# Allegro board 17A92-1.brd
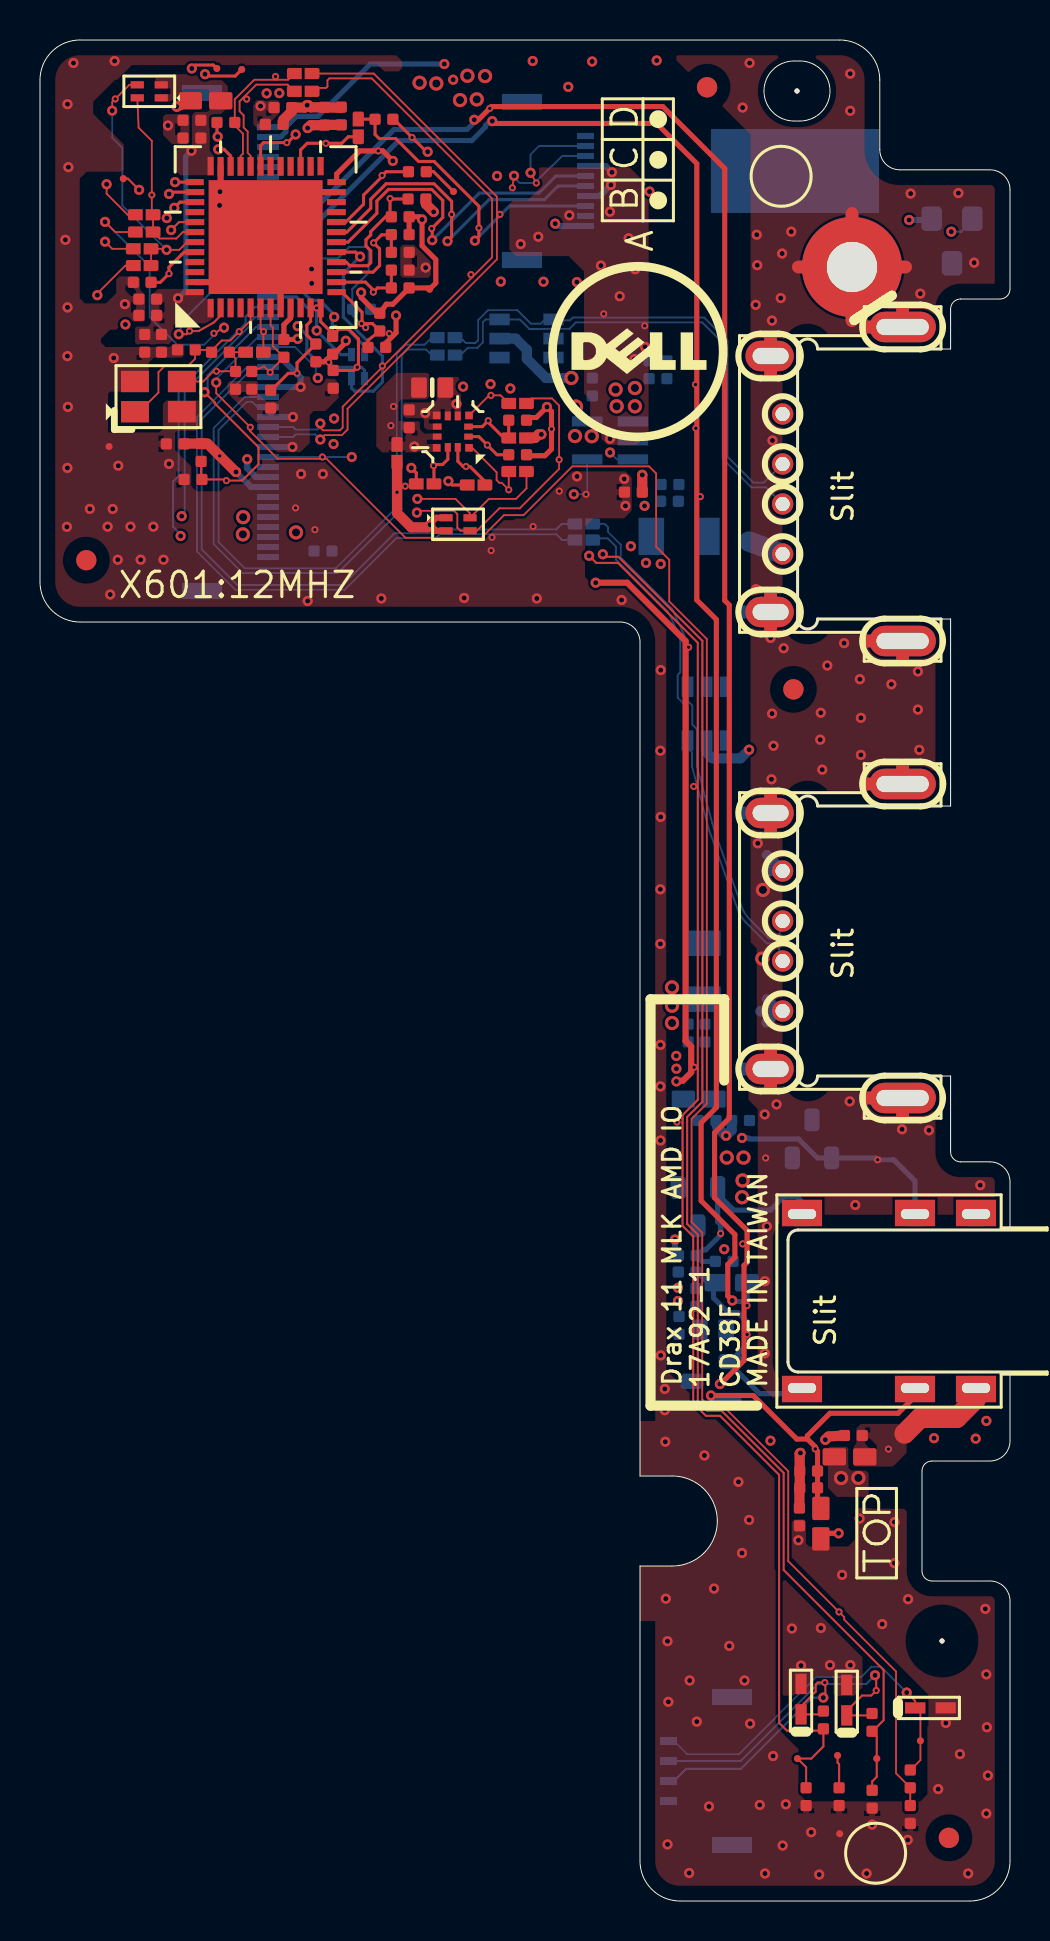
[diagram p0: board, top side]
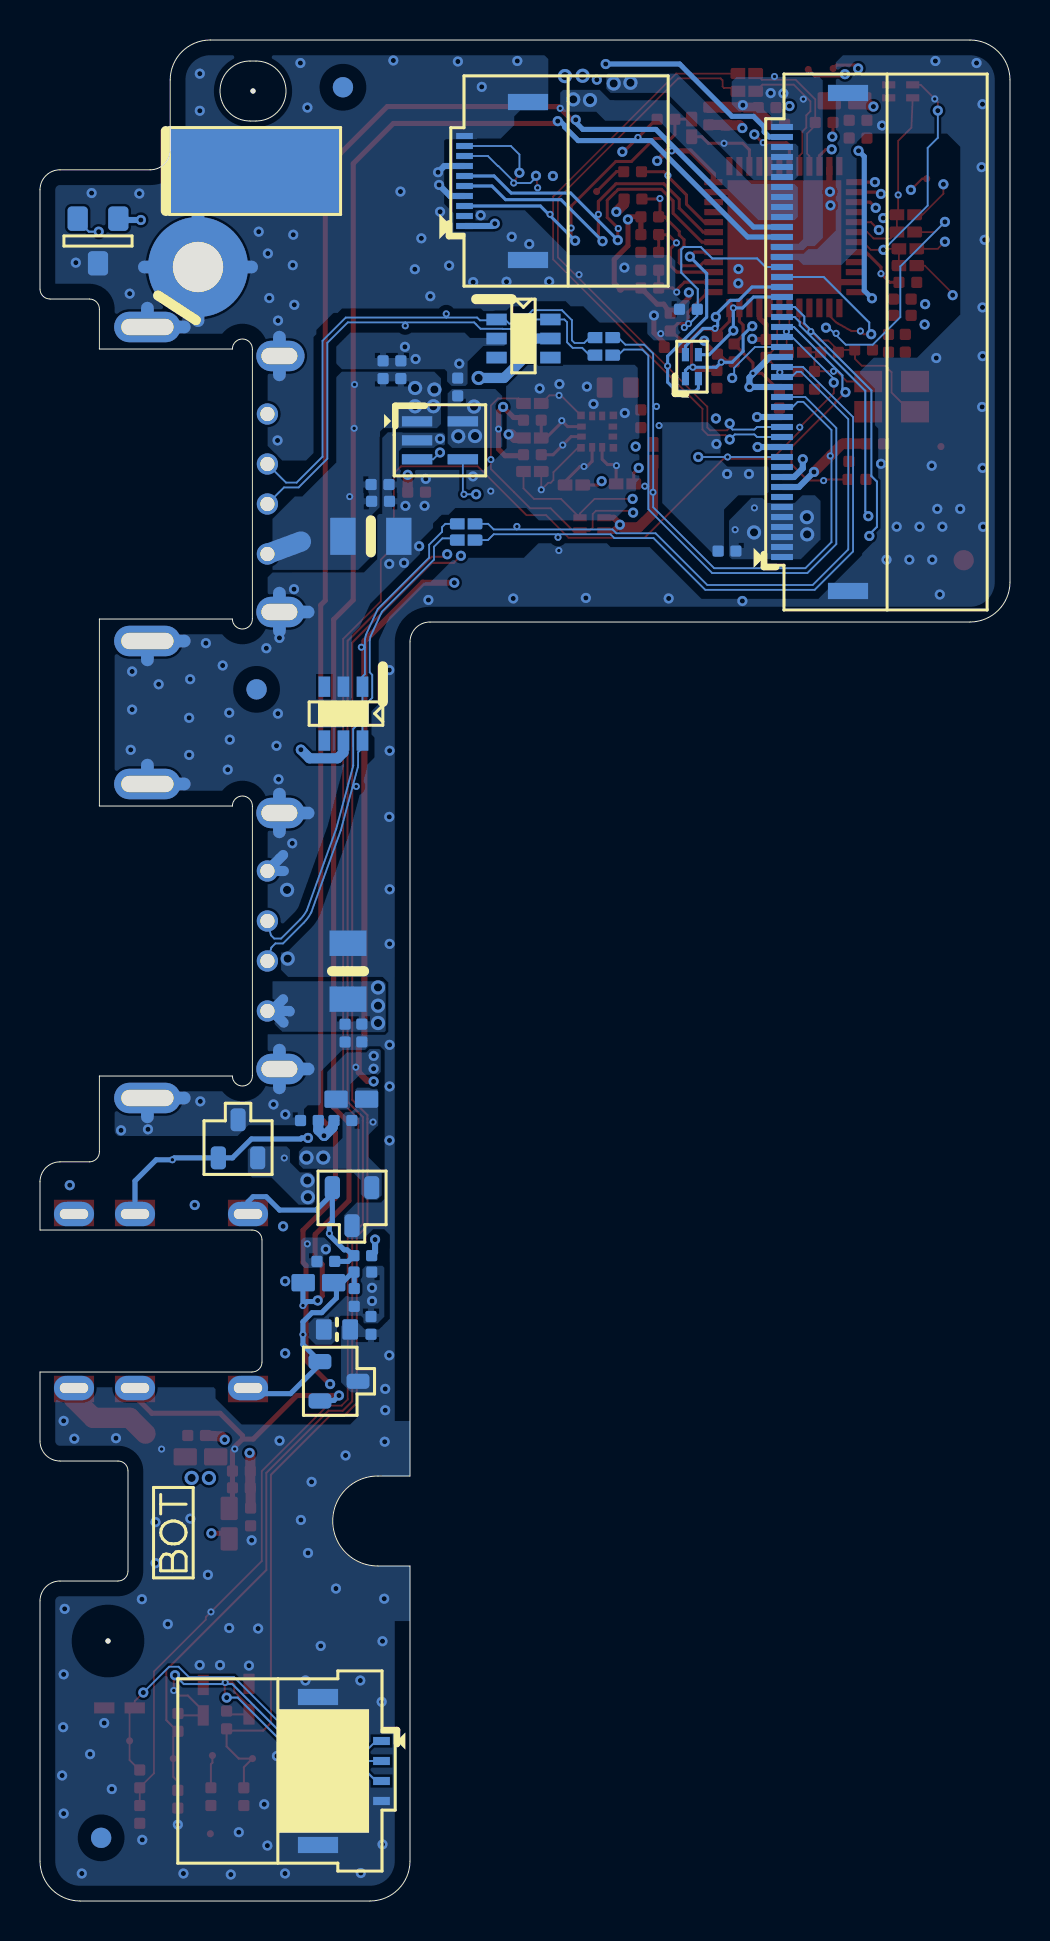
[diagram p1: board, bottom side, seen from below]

Outline 48.5 x 93.05 mm; copper layers: TOP, L2GND, L3, L4, L5VCC, BOTTOM. Coordinates in mm from the lower left corner of the outline.
Outline path: 0,91.05 0,65.95 arc(0.59,64.54) 2,63.95 29,63.95 arc(29.71,63.66) 30,62.95 30,21.25 31.6,21.25 arc(33.85,19) 31.6,16.75 30,16.75 30,2 arc(30.59,0.59) 32,0 46.5,0 arc(47.91,0.59) 48.5,2 48.5,15 arc(48.21,15.71) 47.5,16 44.6,16 arc(44.25,16.15) 44.1,16.5 44.1,21.5 arc(44.25,21.85) 44.6,22 47.5,22 arc(48.21,22.29) 48.5,23 48.5,26.45 37.9,26.45 arc(37.55,26.6) 37.4,26.95 37.4,33.05 arc(37.55,33.4) 37.9,33.55 48.5,33.55 48.5,35.96 arc(48.21,36.66) 47.5,36.96 46.03,36.96 arc(45.68,37.1) 45.53,37.46 45.53,41.25 38.88,41.25 arc(38.38,40.75) 37.88,41.25 37.88,54.75 arc(38.38,55.25) 38.88,54.75 45.53,54.75 45.53,64.1 38.88,64.1 arc(38.38,63.6) 37.88,64.1 37.88,77.6 arc(38.38,78.1) 38.88,77.6 45.53,77.6 45.53,79.6 arc(45.68,79.95) 46.03,80.1 48,80.1 arc(48.35,80.25) 48.5,80.6 48.5,85.56 arc(48.21,86.27) 47.5,86.56 42.99,86.56 arc(42.28,86.85) 41.99,87.56 41.99,91.05 arc(41.4,92.46) 39.99,93.05 2,93.05 arc(0.59,92.46) 0,91.05 ; 37.7,92 38,92 arc(39.5,90.5) 38,89 37.7,89 arc(36.2,90.5) 37.7,92

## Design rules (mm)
constraint set DEFAULT: min track width 0.127, pair gap 0.102
net group HUB_USB20_CON_N7: nets HUB_USB20_CON_N7 USB_2-
net group HUB_USB20_CON_P7: nets HUB_USB20_CON_P7 USB_2+
net group POWER_20M: nets 3D3V_S0 3D3V_S5
net group AUDIO_BEEP: nets AUD_PORTA_L_HPMIC1 AUD_PORTA_L_R_B AUD_PORTA_R_HPMIC1 AUD_PORTA_R_R_B JACK_PLUG JACK_PLUG_DET
net group OTHER: nets KBC_PWRBTN# KBC_PWRBTN#_C USB_OC#0 USB_PWR_EN#
net group OTHER_4: nets HALL_KB_DIS# HALL_KB_DIS#_C KB_RESERVE MODEL_ID SENSOR_KB_DIS VOL_DOWN# VOL_DOWN#_R VOL_UP# VOL_UP#_R
net group SENSOR: nets GSEN2_INT1 GSEN2_INT1_C GSEN2_INT1_R GSEN2_INT2 GSEN2_INT2_C GSEN2_INT2_R GSEN_INT1_BD GSEN_INT2_BD GSEN_INT2_HUB_U GSENSOR_CS GSENSOR_SDO GYRO_DRDY_BD GYRO_DRDY_BD_L GYRO_INT_BD GYRO_INT_BD_L HUB_PA1 HUB_PA2 HUB_PA3 HUB_PA4 HUB_PA5 HUB_PA6 MCU_BOOT0 SWCLK SWDIO USBDISABLE
net group SMBUS_CLK-MW: nets SENSOR_I2C_SCL SENSOR_I2C_SCL_2G SENSOR_I2C_SCL_R ST_SENSOR_I2C_SCL
net group SMBUS_DAT-MW: nets SENSOR_I2C_SDA SENSOR_I2C_SDA_2G SENSOR_I2C_SDA_R ST_SENSOR_I2C_SDA
net group USB_HUB-MWS: nets MCU_RST#
net group XTAL: nets MCU_OSCI MCU_OSCO MCU_OSCO_X601

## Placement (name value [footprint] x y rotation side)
AFTP701  AFTE14P-GP  [AFTE14P-75]  39.98 3.36 0 top
AFTP702  AFTE14P-GP  [AFTE14P-75]  44.02 8.01 0 top
AFTP703  AFTE14P-GP  [AFTE14P-75]  41.84 7.12 0 top
AFTP704  AFTE14P-GP  [AFTE14P-75]  37.87 7.12 0 top
AFTP706  AFTE14P-GP  [AFTE14P-75]  39.88 7.27 0 top
C402  SCD1U16V2KX-3GP  [C402H22]  30.46 76.56 0 bottom
C403  SC1U10V2KX-1GP  [C402H22]  27.61 75.7 0 bottom
C404  SC1U10V2KX-1GP  [C402H22]  31.35 76.56 0 bottom
C405  SC100U6D3V6MX-GP  [C1206H71]  33.1 46.49 0 bottom
C406  SC100U6D3V6MX-GP  [C1206H71]  31.96 68.23 90 bottom
C407  SCD1U16V2KX-3GP  [C402H22]  32.41 43.4 180 bottom
C501  SC10U6D3V3MX-GP  [C603H38]  19.61 75.67 90 top
C502  SCD1U16V2KX-3GP  [C402H22]  18.46 74.11 180 top
C601  SC15P50V2JN-2-GP  [C402H22]  9.78 76.03 0 top
C602  SCD01U50V2KX-1GP  [C402H22]  5.39 80.1 270 top
C603  SC15P50V2JN-2-GP  [C402H22]  7.32 77.56 270 top
C604  SCD1U16V2KX-3GP  [C402H22]  5.39 79.28 270 top
C605  SC1U10V2KX-1GP  [C402H22]  7.6 89.04 270 top
C606  SCD1U16V2KX-3GP  [C402H22]  7.6 88.15 270 top
C607  SCD1U16V2KX-3GP  [C402H22]  6.07 77.89 0 top
C608  SCD1U16V2KX-3GP  [C402H22]  10.59 76.03 0 top
C609  SCD1U16V2KX-3GP  [C402H22]  5.24 77.89 0 top
C610  SCD1U16V2KX-3GP  [C402H22]  6.76 72.86 270 top
C611  SCD047U16V2KX-1-GP  [C402H22]  7.65 71.08 270 top
C702  SC1KP50V2KX-1GP  [C402H22]  38.31 5.22 180 top
C703  SC1KP50V2KX-1GP  [C402H22]  41.61 5.09 180 top
C704  SCD1U25V2KX-GP  [C402H22]  43.51 4.33 0 top
C801  SCD1U10V2KX-L1-GP  [C402H22]  14.15 67.5 270 bottom
EC301  SC680P50V2KX-2DLGP  [C402H22]  33.35 39.02 270 bottom
EC302  SC680P50V2KX-2DLGP  [C402H22]  32.79 30.18 180 bottom
EC303  SC680P50V2KX-2DLGP  [C402H22]  40.67 23.28 270 top
EC304  SC680P50V2KX-2DLGP  [C402H22]  38.43 21.5 270 top
EC401  SCD1U16V2KX-3GP  [C402H22]  31.5 70.82 90 bottom
EC402  SCD1U16V2KX-3GP  [C402H22]  31.47 69.99 90 bottom
EC705  SCD1U16V2KX-3GP  [C402H22]  39.95 5.22 0 top
EC801  SCD1U25V2KX-1-DL-GP  [C402H22]  14.23 89.24 0 top
EC802  SCD1U25V2KX-1-DL-GP  [C402H22]  35.03 39.02 270 bottom
EC803  SCD1U25V2KX-1-DL-GP  [C402H22]  11.71 88.83 270 top
EC804  SCD1U25V2KX-1-DL-GP  [C402H22]  31.95 28.78 180 bottom
EC805  SCD1U25V2KX-1-DL-GP  [C402H22]  15.06 89.25 0 top
EC806  SCD1U25V2KX-1-DL-GP  [C402H22]  12.14 89.67 270 top
EC807  SCD1U25V2KX-1-DL-GP  [C402H22]  37.97 19.2 0 top
EC808  SCD1U25V2KX-1-DL-GP  [C402H22]  29.67 70.44 270 top
ED301  AZ5125-02S-R7G-GP  [SOT23-2D4-312H46]  33.55 25.99 270 bottom
ED302  AZ5125-02S-R7G-GP  [SOT23-2D4-312H46]  38.6 38.11 180 bottom
ED303  AZ5125-02S-R7G-GP  [SOT23-2D4-312H46]  32.9 34.72 0 bottom
ED402  AZC099-04S-2-GP  [SOT-6H58]  24.33 78.12 270 bottom
ED403  AZC099-04S-2-GP  [SOT-6H58]  33.33 59.37 0 bottom
ED701  PESD5V0S1BB-GP-U  [SOD-523-2H26]  44.52 9.65 90 top
ED702  PESD5V0S1BB-GP-U  [SOD-523-2H26]  40.34 10.04 180 top
ED703  PESD5V0S1BB-GP-U  [SOD-523-2H26]  38.05 10.09 180 top
H7  HOLE197R99-GP  [HOLE197R99]  40.6 81.7 0 top
HPMIC1  AUDIO-JK489-GP  [AJ3F7C-YX50-412]  46.8 30 90 top
IOBD2  ACES-CON44-2-GP  [132F44-000000-A2-R]  8.1 77.95 90 bottom
LIDSW2  S-5712ACDL1-M3T1U-GP  [SOT23-2D8-123H52]  45.6 83 0 bottom
NOREF  -  []  29.39 87.82 90 top
NOREF#2  -  []  41.78 2.39 0 top
NOREF#3  *  [unnamed#2]  45.44 3.16 0 top
NOREF#4  -  [unnamed#2]  37.85 90.5 0 top
NOREF#5  -  []  29.89 77.47 0 top
NOREF#6  *  [unnamed#2]  33.35 90.69 0 top
NOREF#7  -  []  -91.9 111 0 top
NOREF#8  -  [unnamed#2]  45.1 13 0 top
NOREF#9  *  [unnamed#2]  2.32 67.04 0 top
NOREF#10  -  []  -91.9 111 0 top
NOREF#11  -  []  41.83 18.39 90 top
NOREF#12  -  []  519.62 509.67 0 top
NOREF#13  *  [unnamed#2]  37.67 60.58 0 top
NOREF#14  -  []  37.06 86.24 0 top
NOREF#15  *  [unnamed#2]  33.35 90.69 180 bottom
NOREF#16  -  []  41.83 18.42 90 bottom
NOREF#17  *  [unnamed#2]  37.67 60.58 180 bottom
NOREF#18  *  [unnamed#2]  45.44 3.16 180 bottom
PWBD1  ACES-CON4-83-GP  [51678-00401-W01]  34.6 6.5 270 bottom
R301  -  [0R0603-PAD]  32.84 40.09 90 bottom
R302  -  [0R0603-PAD]  34.49 30.91 90 bottom
R303  -  [0R0603-PAD]  39.04 18.96 180 top
R304  10KR2J-3-GP  [R402H16]  32.36 31.45 90 bottom
R305  10KR2J-3-GP  [R402H16]  38.43 20.66 270 top
R306  -  [0R0603-PAD]  40.57 22.21 90 top
R307  0R2J-L-GP  [R402H15]  34.21 31.98 270 bottom
R308  0R2J-L-GP  [R402H15]  32.36 32.27 270 bottom
R406  100KR2J-1-GP  [R402H16]  33.25 43.39 180 bottom
R407  -  [0R0402-PAD]  20.31 77.29 270 bottom
R408  -  [0R0402-PAD]  20.31 78.17 270 bottom
R409  -  [0R0402-PAD]  27.19 68.05 270 bottom
R410  -  [0R0402-PAD]  27.19 68.86 270 bottom
R501  -  [0R0402-PAD]  17.85 72.38 180 top
R502  10KR2J-3-GP  [R402H16]  23.88 74.04 270 top
R503  -  [0R0402-PAD]  23.88 73.15 270 top
R504  10KR2J-3-GP  [R402H16]  23.88 72.31 270 top
R505  -  [0R0402-PAD]  21.8 70.8 270 top
R506  -  [0R0402-PAD]  19.25 70.86 270 top
R507  -  [0R0402-PAD]  23.88 71.47 270 top
R508  -  [0R0402-PAD]  23.88 74.88 270 top
R601  -  [0R0402-PAD]  13.16 90.48 270 top
R602  20MR2J-1-GP  [R402H16]  9.02 77.44 270 top
R603  1K5R2F-2-GP  [R402H16]  9.29 88.93 270 top
R604  10KR2J-3-GP  [R402H16]  14.63 77.78 0 top
R605  10KR2J-3-GP  [R402H16]  11.53 75.09 180 top
R606  10KR2J-3-GP  [R402H16]  13.79 77.4 0 top
R607  10KR2J-3-GP  [R402H16]  18.85 85.1 270 top
R608  10KR2J-3-GP  [R402H16]  18.01 82.43 270 top
R609  10KR2J-3-GP  [R402H16]  18.01 84.21 90 top
R610  10KR2J-3-GP  [R402H16]  18.01 81.54 270 top
R611  10KR2J-3-GP  [R402H16]  18.01 83.32 90 top
R612  10KR2J-3-GP  [R402H16]  18.01 80.65 90 top
R613  10KR2J-3-GP  [R402H16]  16.84 77.68 270 top
R614  10KR2J-3-GP  [R402H16]  16.99 78.95 180 top
R615  100KR2J-1-GP  [R402H16]  12.19 77.63 180 top
R616  10KR2J-3-GP  [R402H16]  14.66 76.08 180 top
R617  -  [0R0402-PAD]  13.16 91.37 270 top
R618  20KR2J-L2-GP  [R402H16]  5.11 80.93 270 top
R619  -  [0R0603-PAD]  8.36 90.01 90 top
R620  100KR2J-1-GP  [R402H16]  8.05 72.42 180 top
R621  -  [0R0402-PAD]  5.21 84.31 90 top
R622  -  [0R0402-PAD]  5.21 83.45 90 top
R623  -  [0R0402-PAD]  5.11 82.61 90 top
R624  -  [0R0402-PAD]  5.11 81.77 90 top
R625  -  [0R0402-PAD]  10.72 77.44 270 top
R626  -  [0R0402-PAD]  15.92 88.65 180 top
R627  0R2J-L-GP  [R402H15]  17.2 89.09 270 top
R628  0R2J-L-GP  [R402H15]  18.87 86.46 90 top
R701  470R2J-2-GP  [R402H16]  43.51 6.11 180 top
R702  470R2J-2-GP  [R402H16]  39.17 9.05 180 top
R703  470R2J-2-GP  [R402H16]  41.6 8.93 180 top
R801  0R3J-0-U-GP  [R603H22]  33.65 28.58 90 bottom
R802  10KR2J-3-GP  [R402H16]  16.08 79.59 270 bottom
RN501  SRN2K2J-1-GP  [ARES2H16]  20.9 68.84 270 top
RN601  SRN2K2J-1-GP  [ARES2H16]  5.46 90.48 90 top
RN602  SRN0J-6-GP  [SMD-ARES4H20]  15.9 76.72 180 bottom
SENSB1  ACES-CON10-30-GP-U  [51530-01001-W01]  24.1 86 90 bottom
SPR7  SPRING-U4-GP  [SPR8745-U4H213]  40.1 86.5 0 bottom
TP601  TPAD14-OP-GP  [TPAD14-OP]  4.17 86.12 0 top
TP602  TPAD14-OP-GP  [TPAD14-OP]  19.48 80.59 0 top
TP603  TPAD14-OP-GP  [TPAD14-OP]  3.45 72.72 0 top
TP604  TPAD14-OP-GP  [TPAD14-OP]  10.09 91.58 0 top
TP605  TPAD14-OP-GP  [TPAD14-OP]  8.84 91.63 0 top
TP606  TPAD14-OP-GP  [TPAD14-OP]  20.67 85.47 0 top
U401  G524B2T11U-GP  [SOT-23-5H58]  28.5 73.03 270 bottom
U501  LNG2DMTR-GP  [LGA12G2H40]  20.64 73.47 270 top
U601  STM32L151CBU6TR-3-GP  [QFN48G7-G5D7H26]  11.28 83.19 180 top
USB2  SKT-USB8-189-GP  [SKT-USB8-160139-1]  43.13 70.85 90 top
USB3  SKT-USB8-189-GP  [SKT-USB8-160139-1]  43.13 48 90 top
X601  XTAL-12MHZ-52-GP-U  [OSC-3225-4P-4H36]  5.92 75.22 0 top

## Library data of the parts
AFTP701-AFTP704 AFTP706 = AFTE14P-75: tolerance: ZZ.AFT14.101
C402 C407 C502 C604 C606-C610 EC401 EC402 EC705 = C402H22: tolerance: 78.10421.2FL
C403 C404 C605 = C402H22: tolerance: 78.10523.5FL
C405 C406 = C1206H71: tolerance: 78.10710.52L
C501 = C603H38: tolerance: 78.10610.5BL
C601 C603 = C402H22: tolerance: 78.15034.1FL
C602 = C402H22: tolerance: 78.10324.2FL
C611 = C402H22: tolerance: 78.47321.2FL
C702 C703 = C402H22: tolerance: 78.10224.2FL
C704 = C402H22: tolerance: 78.10422.5FL
C801 = C402H22: tolerance: 78.10423.L1L
EC301-EC304 = C402H22: tolerance: 78.68124.2FLDL
EC801-EC808 = C402H22: tolerance: 78.10422.5FLDL
ED301-ED303 = SOT23-2D4-312H46: tolerance: 75.05125.07D
ED402 ED403 = SOT-6H58: tolerance: 075.09904.0A7C
ED701-ED703 = SOD-523-2H26: tolerance: 83.0005V.0AF
H7 = HOLE197R99: tolerance: ZZ.00PAD.J21
HPMIC1 = AJ3F7C-YX50-412: tolerance: 022.10002.0771
IOBD2 = 132F44-000000-A2-R: tolerance: 020.K0228.0044
LIDSW2 = SOT23-2D8-123H52: tolerance: 74.05712.0BB
PWBD1 = 51678-00401-W01: tolerance: 020.K0206.0004
R301-R303 R306 R619 = 0R0603-PAD: tolerance: ZZ.R0603.ZZZ
R304 R305 R502 R504 R604-R614 R616 R802 = R402H16: tolerance: 63.10334.1DL
R307 R308 R627 R628 = R402H15: tolerance: 63.R0034.L0L
R406 R615 R620 = R402H16: tolerance: 63.10434.1DL
R407-R410 R501 R503 R505-R508 R621-R626 = 0R0402-PAD: tolerance: ZZ.R0402.ZZZ
R601 = 0R0402-PAD: tolerance: ZZ.R0402.ZZZ; signal model: Graser_R601
R602 = R402H16: tolerance: 063.20634.01DV
R603 = R402H16: tolerance: 64.15015.6DL
R617 = 0R0402-PAD: tolerance: ZZ.R0402.ZZZ; signal model: Graser_R617
R618 = R402H16: tolerance: 63.20334.1DL
R701-R703 = R402H16: tolerance: 63.47134.1DL
R801 = R603H22: tolerance: 63.00000.00L
RN501 RN601 = ARES2H16: tolerance: 66.22236.04L
RN602 = SMD-ARES4H20: tolerance: 66.R0036.04L
SENSB1 = 51530-01001-W01: tolerance: 20.K0642.010
SPR7 = SPR8745-U4H213: tolerance: 34.40U07.001
TP601-TP606 = TPAD14-OP: tolerance: ZZ.PAD14.001
U401 = SOT-23-5H58: tolerance: 074.00524.0C9F
U501 = LGA12G2H40: tolerance: 074.LNG2D.00BZ
U601 = QFN48G7-G5D7H26: tolerance: 071.32151.0D0U
USB2 USB3 = SKT-USB8-160139-1: tolerance: 022.10005.0991
X601 = OSC-3225-4P-4H36: tolerance: 82.30006.491

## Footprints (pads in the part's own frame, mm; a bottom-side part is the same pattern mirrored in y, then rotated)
0R0402-PAD
  custom 0.14x0.14 smd: 1(0,0.445) 2(0,-0.445)
0R0603-PAD
  custom 0.216x0.216 smd: 1(0,0.851) 2(0,-0.673)
132F44-000000-A2-R
  rect 0.305x1.092 smd: 1(-10.75,3.3) 2(-10.25,3.3) 3(-9.75,3.3) 4(-9.25,3.3) 5(-8.75,3.3) 6(-8.25,3.3) 7(-7.75,3.3) 8(-7.25,3.3) 9(-6.75,3.3) 10(-6.25,3.3) 11(-5.75,3.3) 12(-5.25,3.3) 13(-4.75,3.3) 14(-4.25,3.3) 15(-3.75,3.3) 16(-3.25,3.3) 17(-2.75,3.3) 18(-2.25,3.3) 19(-1.75,3.3) 20(-1.25,3.3) 21(-0.75,3.3) 22(-0.25,3.3) 23(0.25,3.3) 24(0.75,3.3) 25(1.25,3.3) 26(1.75,3.3) 27(2.25,3.3) 28(2.75,3.3) 29(3.25,3.3) 30(3.75,3.3) 31(4.25,3.3) 32(4.75,3.3) 33(5.25,3.3) 34(5.75,3.3) 35(6.25,3.3) 36(6.75,3.3) 37(7.25,3.3) 38(7.75,3.3) 39(8.25,3.3) 40(8.75,3.3) 41(9.25,3.3) 42(9.75,3.3) 43(10.25,3.3) 44(10.75,3.3)
  rect 0.813x2.007 smd: 45(-12.45,0) 46(12.45,0)
51530-01001-W01
  rect 0.305x0.838 smd: 1(-2.25,3.175) 2(-1.75,3.175) 3(-1.25,3.175) 4(-0.75,3.175) 5(-0.25,3.175) 6(0.25,3.175) 7(0.75,3.175) 8(1.25,3.175) 9(1.75,3.175) 10(2.25,3.175)
  rect 0.813x2.007 smd: 11(-3.95,0) 12(3.95,0)
51678-00401-W01
  rect 0.406x0.838 smd: 1(-1.5,3.175) 2(-0.5,3.175) 3(0.5,3.175) 4(1.5,3.175)
  rect 0.813x2.007 smd: 5(-3.7,0) 6(3.7,0)
AFTE14P-75
  round 0.356 smd: 1(0,0)
AJ3F7C-YX50-412
  rect 1.321x2.007 hole 0.508x1.422: 1(-4.35,0) 2(4.35,0) 3(-4.35,3.05) 4(-4.35,8.7) 5(4.35,3.05) 6(4.35,8.7)
ARES2H16
  rect 0.356x0.66 smd: 1(-0.325,-0.599) 2(0.325,-0.599) 3(0.325,0.599) 4(-0.325,0.599)
C402H22
  custom 0.14x0.14 smd: 1(0,0.445) 2(0,-0.445)
C603H38
  custom 0.197x0.197 smd: 1(0,0.66) 2(0,-0.66)
C1206H71
  rect 1.854x1.27 smd: 1(0,1.397) 2(0,-1.397)
HOLE197R99
  round 5.004 hole 2.515: 1(0,0)
LGA12G2H40
  rect 0.381x0.381 smd: 1(0.809,0.809) 4(-0.809,0.809) 7(-0.809,-0.809) 10(0.809,-0.809)
  rect 0.305x0.432 smd: 2(0.25,0.784) 3(-0.25,0.784) 8(-0.25,-0.784) 9(0.25,-0.784)
  rect 0.432x0.305 smd: 5(-0.784,0.25) 6(-0.784,-0.25) 11(0.784,-0.25) 12(0.784,0.25)
OSC-3225-4P-4H36
  rect 1.397x1.067 smd: 1(-1.171,-0.756) 2(1.171,-0.756) 3(1.171,0.756) 4(-1.171,0.756)
QFN48G7-G5D7H26
  rect 0.305x0.914 smd: 1(2.75,3.551) 12(-2.75,3.551) 25(-2.75,-3.551) 36(2.75,-3.551)
  rect 0.305x0.94 smd: 2(2.25,3.538) 3(1.75,3.538) 4(1.25,3.538) 5(0.75,3.538) 6(0.25,3.538) 7(-0.25,3.538) 8(-0.75,3.538) 9(-1.25,3.538) 10(-1.75,3.538) 11(-2.25,3.538) 26(-2.25,-3.538) 27(-1.75,-3.538) 28(-1.25,-3.538) 29(-0.75,-3.538) 30(-0.25,-3.538) 31(0.25,-3.538) 32(0.75,-3.538) 33(1.25,-3.538) 34(1.75,-3.538) 35(2.25,-3.538)
  rect 0.914x0.305 smd: 13(-3.551,2.75) 24(-3.551,-2.75) 37(3.551,-2.75) 48(3.551,2.75)
  rect 0.94x0.305 smd: 14(-3.538,2.25) 15(-3.538,1.75) 16(-3.538,1.25) 17(-3.538,0.75) 18(-3.538,0.25) 19(-3.538,-0.25) 20(-3.538,-0.75) 21(-3.538,-1.25) 22(-3.538,-1.75) 23(-3.538,-2.25) 38(3.538,-2.25) 39(3.538,-1.75) 40(3.538,-1.25) 41(3.538,-0.75) 42(3.538,-0.25) 43(3.538,0.25) 44(3.538,0.75) 45(3.538,1.25) 46(3.538,1.75) 47(3.538,2.25)
  rect 5.69x5.69 smd: 49(0,0)
R402H15
  custom 0.14x0.14 smd: 1(0,0.445) 2(0,-0.445)
R402H16
  custom 0.14x0.14 smd: 1(0,0.445) 2(0,-0.445)
R603H22
  custom 0.197x0.197 smd: 1(0,0.66) 2(0,-0.66)
SKT-USB8-160139-1
  round 1.067 hole 0.711: 1(-3.5,6) 2(-1,6) 3(1,6) 4(3.5,6)
  oval 1.524x2.413 hole 0.813x1.803: 5(6.4,6.6) 6(-6.4,6.6)
  oval 1.524x3.327 hole 0.813x2.616: 7(7.85,0) 8(-7.85,0)
SMD-ARES4H20
  rect 0.356x0.66 smd: 1(-0.325,-0.599) 2(0.325,-0.599) 3(0.325,0.599) 4(-0.325,0.599)
SOD-523-2H26
  rect 0.559x1.016 smd: 1(0,0.762) 2(0,-0.762)
SOT23-2D4-312H46
  custom 0.191x0.191 smd: 1(-0.984,-0.953) 2(0.984,-0.953) 3(0,0.953)
SOT23-2D8-123H52
  custom 0.254x0.254 smd: 1(0,1.118) 2(-1.016,-1.118) 3(1.016,-1.118)
SOT-6H58
  rect 0.584x1.016 smd: 1(-0.953,-1.346) 2(0,-1.346) 3(0.953,-1.346) 4(0.953,1.346) 5(0,1.346) 6(-0.953,1.346)
SOT-23-5H58
  rect 0.508x1.524 smd: 1(-0.95,-1.143) 2(0,-1.143) 3(0.95,-1.143) 4(0.95,1.143) 5(-0.95,1.143)
SPR8745-U4H213
  rect 8.407x4.191 smd: 1(-1.994,0)
TPAD14-OP
  round 0.356 smd: 1(0,0)
unnamed#2
  round 1.016 smd: (0,0)

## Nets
5V_S5: C403.1 C801.1 IOBD2.1 IOBD2.2 IOBD2.3 IOBD2.4 IOBD2.5 IOBD2.6 U401.5
GND: AFTP701.1 C402.2 C403.2 C404.2 C405.2 C406.2 C407.2 C501.2 C502.2 C601.2 C602.2 C603.2 C604.2 C605.2 C606.2 C607.2 C608.2 C609.2 C610.2 C611.2 C702.1 C703.1 C704.2 C801.2 EC401.2 EC402.2 EC705.2 EC801.2 EC802.2 EC803.2 EC804.2 EC805.2 EC806.2 EC807.2 EC808.2 ED301.3 ED302.3 ED303.3 ED402.2 ED403.2 ED701.2 ED702.2 ED703.2 H7.1 IOBD2.12 IOBD2.15 IOBD2.18 IOBD2.21 IOBD2.31 IOBD2.45 IOBD2.46 LIDSW2.1 PWBD1.4 PWBD1.5 PWBD1.6 R406.2 R503.1 R605.1 R607.1 R608.1 R610.1 R613.1 R616.1 R618.2 R801.2 R802.2 SENSB1.4 SENSB1.7 SENSB1.10 SENSB1.11 SENSB1.12 SPR7.1 TP603.1 U401.2 U501.5 U501.6 U501.7 U501.8 U601.8 U601.23 U601.35 U601.47 U601.49 USB2.4 USB2.5 USB2.6 USB2.7 USB2.8 USB3.4 USB3.5 USB3.6 USB3.7 USB3.8 X601.2 X601.4
3D3V_GSEN2: C501.1 C502.1 R501.2 R502.1 R504.1 U501.9 U501.10
3D3V_MCU: C602.1 C604.1 C605.1 C606.1 C607.1 C609.1 R604.2 R606.2 R609.2 R611.2 R612.2 R614.2 R615.2 R619.2 RN601.1(A) RN601.2(A) TP602.1 U601.1 U601.9 U601.24 U601.36 U601.48
3D3V_S0: IOBD2.9 R308.1 R501.1 R619.1 RN501.1(A) RN501.2(A) SENSB1.1
3D3V_S5: C610.1 IOBD2.8 LIDSW2.2 R620.2
AUD_AGND: EC301.2 EC302.2 EC303.2 EC304.2 EC801.1 EC802.1 EC803.1 EC804.1 EC805.1 EC806.1 EC807.1 EC808.1 IOBD2.32 IOBD2.44 R304.2 R305.2 R307.2 R801.1
AUD_PORTA_L_HPMIC1: EC302.1 ED301.1 HPMIC1.4 R302.2 R304.1
AUD_PORTA_L_R_B: IOBD2.33 R302.1
AUD_PORTA_R_HPMIC1: EC304.1 ED301.2 HPMIC1.3 R303.2 R305.1
AUD_PORTA_R_R_B: IOBD2.34 R303.1
GSEN2_INT1: IOBD2.27 R505.2 RN602.3(B)
GSEN2_INT1_C: RN602.2(A) U601.17
GSEN2_INT1_R: R505.1 U501.12
GSEN2_INT2: IOBD2.28 R506.2 RN602.4(B)
GSEN2_INT2_C: RN602.1(A) U601.38
GSEN2_INT2_R: R506.1 U501.11
GSEN_INT1_BD: SENSB1.6 U601.18
GSEN_INT2_BD: SENSB1.5 U601.19
GSEN_INT2_HUB_U: R626.1 U601.27
GSENSOR_CS: R504.2 U501.2
GSENSOR_SDO: R502.2 R503.2 U501.3
GYRO_DRDY_BD: R626.2 R627.2 SENSB1.3
GYRO_DRDY_BD_L: R627.1 U601.39
GYRO_INT_BD: R628.2 TP606.1
GYRO_INT_BD_L: R628.1 U601.20
HALL_KB_DIS#: C611.1 IOBD2.24 LIDSW2.3 R620.1
HALL_KB_DIS#_C: AFTP706.1 EC705.1
HUB_PA1: R605.2 R606.1 U601.11
HUB_PA2: R604.1 R616.2 U601.12
HUB_PA3: R613.2 R614.1 U601.13
HUB_PA4: R610.2 R612.1 U601.14
HUB_PA5: R608.2 R611.1 U601.15
HUB_PA6: R607.2 R609.1 U601.16
HUB_USB20_CON_N7: IOBD2.14 R601.1
HUB_USB20_CON_P7: IOBD2.13 R617.1
JACK_PLUG: ED302.1 HPMIC1.5 IOBD2.43
JACK_PLUG_DET: ED303.2 HPMIC1.6 R307.1 R308.2
KB_RESERVE: TP601.1 U601.41
KBC_PWRBTN#: C704.1 IOBD2.23 R701.1
KBC_PWRBTN#_C: AFTP702.1 ED701.1 PWBD1.1 R701.2
MCU_BOOT0: R618.1 U601.44
MCU_OSCI: C603.1 R602.2 U601.5 X601.1
MCU_OSCO: R625.1 U601.6
MCU_OSCO_X601: C601.1 R602.1 R625.2 X601.3
MCU_RST#: C608.1 R615.1 U601.7
MODEL_ID: IOBD2.30 R802.1
RING2_HPMIC1: EC301.1 ED303.1 HPMIC1.2 R301.2
RING2_R: IOBD2.39 IOBD2.40 IOBD2.41 IOBD2.42 R301.1
SENSOR_I2C_SCL: R507.1 R622.1 RN501.4(B)
SENSOR_I2C_SCL_2G: R621.2 R622.2 RN601.4(B) U601.42
SENSOR_I2C_SCL_R: R507.2 U501.1
SENSOR_I2C_SDA: R508.1 R624.1 RN501.3(B)
SENSOR_I2C_SDA_2G: R623.2 R624.2 RN601.3(B) U601.43
SENSOR_I2C_SDA_R: R508.2 U501.4
SENSOR_KB_DIS: IOBD2.29 U601.2
SLEEVE_HPMIC1: EC303.1 HPMIC1.1 R306.2
SLEEVE_R: ED302.2 IOBD2.35 IOBD2.36 IOBD2.37 IOBD2.38 R306.1
ST_SENSOR_I2C_SCL: R621.1 SENSB1.8
ST_SENSOR_I2C_SDA: R623.1 SENSB1.9
SWCLK: TP604.1 U601.37
SWDIO: TP605.1 U601.34
USB2_USB20_CON_N3: ED402.6 R407.2 USB2.2
USB2_USB20_CON_P3: ED402.1 R408.2 USB2.3
USB2_USB20_N3: IOBD2.17 R407.1
USB2_USB20_P3: IOBD2.16 R408.1
USB3_USB20_CON_N4: ED403.6 R409.2 USB3.2
USB3_USB20_CON_P4: ED403.1 R410.2 USB3.3
USB3_USB20_N4: IOBD2.20 R409.1
USB3_USB20_P4: IOBD2.19 R410.1
USB20_VCCA: C402.1 C404.1 C405.1 C406.1 C407.1 EC401.1 EC402.1 ED402.5 ED403.5 R406.1 U401.1 USB2.1 USB3.1
USB_2+: R603.1 R617.2 U601.33
USB_2-: R601.2 U601.32
USB_OC#0: IOBD2.11 U401.3
USB_PWR_EN#: IOBD2.22 U401.4
USBDISABLE: R603.2 U601.31
VOL_DOWN#: AFTP704.1 C702.2 IOBD2.26 R702.1
VOL_DOWN#_R: ED703.1 PWBD1.3 R702.2
VOL_UP#: AFTP703.1 C703.2 IOBD2.25 R703.1
VOL_UP#_R: ED702.1 PWBD1.2 R703.2

Pads without a net: ED402 3 4; ED403 3 4; IOBD2 7 10; SENSB1 2; U601 3 4 10 21 22 25 26 28 29 30 40 45 46

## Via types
v1: diameter 0.356, hole 0.178, TOP to BOTTOM, 79 vias
v2: diameter 0.508, hole 0.254, TOP to BOTTOM, 279 vias
v3: diameter 0.711, hole 0.406, TOP to BOTTOM, 28 vias

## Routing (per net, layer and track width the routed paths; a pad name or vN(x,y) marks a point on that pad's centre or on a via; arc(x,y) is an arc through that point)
5V_S5:
  vias: v1(12.78,69.66) v1(13.74,68.56) v3(10.14,68.33) v3(10.16,69.19) v3(12.8,68.43) v3(26.75,73.25) v3(26.8,74.72) v3(27.59,73.24)
GND: length 144.4
  TOP w0.254: v2(17.8,79.28) 17.8,78.41 17.29,77.9 R613.1
  TOP w0.305: U601.35 9.03,85.44 ; U601.47 8.8,80.94 ; U601.8 12.03,80.59 ; U601.23 13.68,85.44
  TOP w0.508: R503.1 24.75,73.15 24.93,73.33 v2(25.07,73.33) ; v2(13.38,88.65) 13.53,88.79 EC801.2 14.24,88.81 EC805.2 ; R607.1 19.29,84.85 v2(19.68,84.46)
  TOP w0.635: 43.13,56.79 USB3.7 41.29,55.85 ; 43.13,62.06 USB2.8 41.29,63 ; 41.29,40.15 USB3.8 43.13,39.21 ; 36.53,53.46 USB3.5 36.53,55.34 ; 36.53,78.19 USB2.5 36.53,76.31 ; 40.6,79.02 H7.1 ; H7.1 37.92,81.7 ; H7.1 43.28,81.7 ; H7.1 40.6,84.38 ; 36.53,42.54 USB3.6 36.53,40.66 ; 41.29,78.7 USB2.7 43.13,79.64 ; 36.53,63.51 USB2.6 36.53,65.39
  L3 w0.635: 43.13,79.64 USB2.7 41.29,78.7 ; 38.96,81.7 H7.1 ; H7.1 40.6,80.06 ; H7.1 40.6,83.34 ; H7.1 42.24,81.7 ; 43.13,39.21 USB3.8 41.29,40.15 ; 36.53,63.51 USB2.6 36.53,65.39 ; 41.29,63 USB2.8 43.13,62.06 ; 36.53,40.66 USB3.6 36.53,42.54 ; 36.53,55.34 USB3.5 36.53,53.46 ; 41.29,55.85 USB3.7 43.13,56.79 ; 36.53,76.31 USB2.5 36.53,78.19
  L4 w0.508: 36.53,64.05 36.53,63.16 v2(36.53,63.15) ; 36.53,64.05 USB2.6 ; 36.53,64.05 35.89,63.42 ; 36.42,52.2 36.43,52.2 USB3.4 36.28,51.5 36.27,51.49 ; 36.48,75 USB2.4
  L4 w0.635: 35.09,77.25 USB2.5 ; USB2.5 36.53,76.31 ; USB2.5 36.53,78.19 ; 35.09,64.45 USB2.6 36.53,65.39 ; H7.1 42.24,81.7 ; H7.1 40.6,80.06 ; H7.1 40.6,83.34 ; H7.1 38.96,81.7 ; 43.13,62.06 USB2.8 41.29,63 ; 41.29,55.85 USB3.7 43.13,56.79 ; 36.53,40.66 USB3.6 ; USB3.6 35.09,41.6 ; USB3.6 36.53,42.54 ; 36.53,53.46 USB3.5 ; USB3.5 35.09,54.4 ; USB3.5 36.53,55.34 ; 43.13,39.21 USB3.8 41.29,40.15 ; 43.13,79.64 USB2.7 41.29,78.7
  BOTTOM w0.305: v2(28.55,85.8) 27.99,85.25 SENSB1.4 ; v2(12.62,72.7) IOBD2.12 ; v2(28.6,86.44) 28.28,86.75 SENSB1.7 ; v2(12.65,74.2) IOBD2.15 ; IOBD2.21 12,77.2 13.03,76.18 v2(13.03,75.7) IOBD2.18
  BOTTOM w0.508: 36.31,51.5 USB3.4 37.13,51.52 36.34,52.3
  BOTTOM w0.635: 41.29,55.85 USB3.7 43.13,56.79 ; USB3.5 36.53,55.34 ; USB3.5 35.09,54.4 ; USB3.5 36.53,53.46 ; 36.53,63.51 USB2.6 ; USB2.6 35.09,64.45 ; USB2.6 36.53,65.39 ; 36.53,76.31 USB2.5 36.53,78.19 ; H7.1 43.28,81.7 ; H7.1 40.6,84.38 ; H7.1 37.92,81.7 ; H7.1 40.6,79.02 ; 43.13,79.64 USB2.7 41.29,78.7 ; 41.29,63 USB2.8 43.13,62.06 ; 35.09,41.6 USB3.6 ; USB3.6 36.53,42.54 ; USB3.6 36.53,40.66 ; 43.13,39.21 USB3.8 41.29,40.15
  vias: v1(17.46,78.37) v1(22.56,67.52) v1(25.96,70.49) v2(1.27,83.06) v2(1.34,68.71) v2(1.38,89.84) v2(1.42,86.69) v2(1.38,79.68) v2(1.37,77.24) v2(1.39,74.7) v2(1.37,71.66) v2(1.67,91.9) v2(2.49,69.61) v2(3.38,68.72) v2(3.51,65.33) v2(3.63,69.61) v2(3.73,92) v2(3.69,77.15) v2(3.91,71.76) v2(3.89,67.07) v2(4.24,79.84) v2(4.27,78.83) v2(4.52,68.72) v2(5.03,67.07) v2(5.67,68.72) v2(6.17,67.07) v2(6.34,84.15) v2(6.4,88.78) v2(6.45,71.86) v2(9,85.46) v2(8.98,84.78) v2(11.03,89.75) v2(13.05,71.35) v2(13.38,65) v2(13.58,81.6) v2(13.59,80.88) v2(14.15,71.35) v2(14.7,74.13) v2(14.68,72.85) v2(17.07,65.13) v2(19.28,81.67) v2(19.26,74.4) v2(20.83,74.85) v2(21.16,75.72) v2(21.21,65.15) v2(22.53,75.85) v2(22.85,86.25) v2(23.04,80.97) v2(23.52,75.62) v2(24.04,82.85) v2(24.64,92) v2(24.84,65.13) v2(24.91,83.21) v2(25.17,80.96) v2(26.41,90.71) v2(26.47,84.28) v2(26.84,80.94) v2(26.85,71.23) v2(27.54,76.87) v2(27.61,91.98) v2(28.04,81.77) v2(28.5,84.46) v2(28.5,73.11) v2(28.99,80.24) v2(29.08,65.05) v2(29.21,71.11) v2(29.27,69.76) v2(29.43,83.13) v2(29.54,67.74) v2(29.72,77.1) v2(29.76,81.59) v2(30.23,69.76) v2(30.25,77.71) v2(30.3,66.91) v2(30.48,85.47) v2(30.83,92.03) v2(31.04,66.85) v2(31.04,61.55) v2(31.02,57.51) v2(31.04,54.21) v2(31.02,50.58) v2(31.02,47.86) v2(31.02,42.81) v2(31.02,40.73) v2(31.03,38.03) v2(31.04,27.28) v2(31.24,25.61) v2(31.24,24.54) v2(31.26,22.96) v2(31.29,15.12) v2(31.38,12.99) v2(31.42,9.96) v2(31.38,2.83) v2(32.48,11.03) v2(32.46,1.4) v2(32.84,8.97) v2(33.22,22.28) v2(33.45,4.73) v2(33.7,15.62) v2(34.47,12.75) v2(34.92,20.96) v2(35.13,89.67) v2(35.1,17.4) v2(35.23,11.03) v2(35.48,91.9) v2(35.46,19.05) v2(35.51,8.87) v2(35.84,83.31) v2(35.79,79.81) v2(35.8,65.59) v2(35.86,81.79) v2(35.89,52.88) v2(35.99,4.8) v2(36.24,39.33) v2(36.24,30.99) v2(36.24,27.38) v2(36.25,1.38) v2(36.34,33.73) v2(36.52,23.01) v2(36.6,79.02) v2(36.62,73.03) v2(36.6,59.37) v2(36.57,56.09) v2(36.67,57.76) v2(36.65,7.25) v2(36.83,39.83) v2(37.04,80.15) v2(37.11,82.37) v2(37.13,2.77) v2(37.18,62.64) v2(37.29,4.84) v2(37.56,83.47) v2(37.59,13.62) v2(37.92,18.04) v2(38.05,11.77) v2(38.56,3.44) v2(39.04,59.41) v2(39.01,58.07) v2(39.04,13.65) v2(38.96,1.32) v2(39.11,56.57) v2(39.37,61.77) v2(39.5,11.79) v2(40.1,16.31) v2(40.21,62.89) v2(40.51,91.37) v2(40.51,89.51) v2(40.48,39.98) v2(40.52,11.79) v2(40.76,34.8) v2(40.99,61.09) v2(41.04,59.16) v2(41.04,57.3) v2(40.98,19.12) v2(41.33,1.38) v2(41.61,3.82) v2(42.11,13.85) v2(42.57,60.84) v2(42.72,18.95) v2(42.72,16.89) v2(43.1,38.58) v2(43.41,15.09) v2(43.39,3.06) v2(43.53,85.37) v2(43.89,61.48) v2(43.89,59.57) v2(44.02,80.37) v2(43.96,57.56) v2(44.45,38.53) v2(44.7,23.14) v2(44.91,5.6) v2(45.29,8.9) v2(45.92,85.4) v2(46,7.34) v2(46.41,1.38) v2(46.71,81.92) v2(46.78,23.12) v2(47.01,35.79) v2(47.32,24.01) v2(47.27,14.61) v2(47.32,11.33) v2(47.34,8.69) v2(47.32,4.37) v2(47.39,6.28) v3(36.15,50.56) v3(36.12,47.12)
3D3V_GSEN2: length 15.2
  TOP w0.254: R504.1 24.37,72.27 25.25,72.27 25.58,72.59 v1(25.58,73.6) 25.58,74.47 v2(25.35,74.7) 24.82,74.17 24.46,74.17 R502.1
  L4 w0.254: v2(18.72,72.72) 18.72,72.27 19.3,71.68 24.94,71.68 25.58,72.32 25.58,74.47 v2(25.35,74.7)
  vias: v1(17.55,73.77)
3D3V_MCU: length 41.9
  TOP w0.254: R606.2 14.2,76.96 R604.2 14.75,77.39 15.29,77.93 v2(15.29,78.01) ; U601.24 14.83,86.35 15.99,87.51 v1(16.91,87.51) 17.14,87.51 v2(17.64,87.01) ; v2(16.06,80.43) 16.06,80.17 16.84,79.38 R614.2 17.31,79.84 17.64,79.84 R612.2 19.41,80.65 TP602.1 19.79,80.9 19.79,82.08 19.1,82.76 v2(19.1,84.08) 18.97,84.21 R609.2 R611.2 ; U601.9 12.53,79.15 12.19,78.81 R615.2 12.82,78.08 12.86,78.11 v2(12.89,78.11)
  L3 w0.254: v2(17.64,87.01) 17.77,87.01 19.07,85.7 19.07,84.11 v2(19.1,84.08) ; v2(6.9,80.14) 6.9,79.88 8.82,77.96 12.74,77.96 v2(12.89,78.11) 12.98,78.01 v2(15.29,78.01) 15.29,79.66 v2(16.06,80.43)
  BOTTOM w0.254: v2(6.9,80.14) 7.29,80.52 7.29,87.23 v2(7.57,87.51)
3D3V_S0: length 125.5
  TOP w0.305: RN501.2 19.81,68.51 v2(19.51,68.81) 19.58,68.89 19.58,68.93 19.81,69.16 RN501.1 ; v2(31.82,40.98) 31.95,40.98 31.99,41.01 32.14,41.01 32.56,41.43 32.56,42.72 32.28,43 32.28,62.99 29.36,65.92 v2(27.78,65.92)
  TOP w0.508: v2(19.51,68.81) 19.38,68.68 18.56,68.68 17.85,69.4 v1(17.85,70.44) R501.1 ; R619.1 6.85,89.72 v2(6.83,89.72)
  L3 w0.305: v2(31.75,33.07) 31.75,34.56 31.71,34.6 31.71,40.73 31.82,40.84 v2(31.82,40.98) ; v2(27.78,65.92) 28.67,66.8 28.67,67.56 27.42,68.81 v2(19.51,68.81) 19.43,68.89 18.62,68.89 18.17,69.34 11.91,69.34 10.49,70.77 10.49,71.96 v2(10.36,72.09)
  L4 w0.508: v2(6.83,89.72) 7.03,89.52 7.03,88.51 4.71,86.19 4.69,86.19 4.32,85.82 4.32,83.26 5.46,82.12 5.46,74.22 8.87,70.82 10.06,70.82 10.44,71.19 10.44,72.01 v2(10.36,72.09) 9.39,72.09 6.96,74.52 6.96,77.26 7.67,77.98 7.67,78.4 9.41,80.14 13.78,80.14 15.37,81.73 15.37,82.48 16.22,83.33 16.86,83.33 18.62,85.09 21.95,85.09 23.18,83.87 v2(25.76,83.87)
  BOTTOM w0.305: R308.1 31.75,32.44 v2(31.75,33.07) ; v2(25.76,83.87) 25.88,83.75 SENSB1.1 ; v2(10.36,72.09) 10.36,71.63 10.79,71.2 IOBD2.9
3D3V_S5: length 57.7
  TOP w0.508: v2(9.8,71.45) 9.79,71.45 v1(8.99,72.25) 8.37,72.87 R620.2 7.22,72.87 C610.1
  L4 w0.508: v2(9.8,71.45) 9.13,71.45 6.27,74.31 6.27,80.46 7.07,81.27 12.35,81.27 13.31,82.23 14.21,82.23 15.94,83.96 16.6,83.96 18.98,86.34 21.75,86.34 22.93,85.17 28.82,85.17 29.25,84.74 42.77,84.74 v2(43.46,84.05)
  BOTTOM w0.305: v2(9.8,71.45) 10.55,70.7 IOBD2.8 ; LIDSW2.2 44.52,84.05 v2(43.46,84.05)
AUD_AGND: length 10.1
  TOP w0.508: EC805.1 15.05,89.66 EC801.1 13.52,89.68 13.42,89.79 v2(13.36,89.79) 13.24,89.67 EC806.1 12.59,89.48 12.17,89.06 12.17,88.91 EC803.1 ; EC303.2 39.43,23.22 v2(39.27,23.07) ; v2(30.11,71.31) EC808.1 ; EC807.1 37.97,20.64 R305.2 EC304.2 37.98,22.36 v2(38.02,22.4)
  BOTTOM w0.508: EC301.2 33.87,38.67 34.28,38.26 v2(34.3,38.26) 34.58,38.55 EC802.1
  vias: v1(35.14,32.86) v2(11.33,90.38) v2(11.97,90.39) v2(20.66,91.06) v2(31.9,30.66) v2(31.9,30) v2(34.21,32.59) v3(21.37,91.26) v3(22.25,91.25)
AUD_PORTA_L_HPMIC1: length 11.9
  BOTTOM w0.254: EC302.1 32.79,31.43 R304.1 32.86,31.45 33.39,30.91 R302.2 33.68,30.85 33.68,30.15 34.41,29.42 34.9,29.42 35.35,28.96 v1(35.35,28.32) 35.35,27.82 ED301.1 34.5,26.84 35.97,25.37 37.82,25.37 HPMIC1.4
AUD_PORTA_L_R_B: length 85.3
  TOP w0.254: v2(34.62,30.02) 34.39,30.25 34.39,31.83 34.74,32.18 34.74,33.32 33.06,35.01 33.06,38.91 33.82,39.67 33.82,39.75 33.82,64.07 32.84,65.05 32.84,86.87 30.83,88.88 22.73,88.88 v2(22.61,88.99)
  BOTTOM w0.254: v2(34.62,30.02) 34.67,29.97 35.15,29.97 v1(35.35,29.77) 35.35,30.82 R302.1 ; v2(22.61,88.99) 22.49,88.99 22.27,88.77 22.27,88.7 21.59,88.02 17.94,88.02 13.12,83.2 IOBD2.33
AUD_PORTA_R_HPMIC1: length 17.3
  TOP w0.254: R303.2 38.88,19.8 R305.1 EC304.1 38.88,22.49 v1(38.76,22.6) 38.76,22.71 38.37,23.1 ; HPMIC1.3 43.75,25.23 42.91,24.39 39.49,24.39 38.37,23.26 38.37,23.1 ; 38.37,23.1 37.84,23.1 35.66,25.28 v2(33.55,25.28)
  BOTTOM w0.254: ED301.2 33.8,25.03 33.57,25.28 v2(33.55,25.28)
AUD_PORTA_R_R_B: length 100
  TOP w0.254: R303.1 39.32,18.39 v2(39.93,18.39) ; v2(34,25.85) 34.06,25.91 34.08,25.91 35.2,27.03 35.2,31.78 35.35,31.93 35.35,33.53 33.73,35.16 33.73,38.41 34.47,39.14 34.47,64.8 34.24,65.03 34.24,86.62 31.14,89.72 22.58,89.72 v1(22.49,89.63) 21.92,89.06 v2(21.71,89.06)
  L3 w0.254: v2(39.93,18.39) 39.93,18.59 34.06,24.46 34.06,25.78 v2(34,25.85)
  BOTTOM w0.254: IOBD2.34 12.82,83.7 17.7,88.58 21.36,88.58 21.71,88.93 21.71,89.05 v2(21.71,89.06)
GSEN2_INT1: length 19
  TOP w0.152: v2(20.42,70.99) 20.61,70.8 R505.2
  L4 w0.152: v2(13.83,78.52) 14.4,77.96 14.4,75.08 15.16,74.32 15.16,73.41 17.19,71.38 18.01,71.38 18.4,70.99 v2(20.42,70.99)
  BOTTOM w0.152: IOBD2.27 12.83,80.2 13.37,79.65 v1(13.83,79.65) v2(13.83,78.52) 15.04,77.32 RN602.3
GSEN2_INT1_C: length 11
  TOP w0.152: v2(16.01,82.22) 15.78,82.44 U601.17
  BOTTOM w0.152: RN602.2 15.58,75.64 15.73,75.49 16.67,75.49 17.12,75.94 v1(17.12,76.75) 17.12,77.25 15.17,79.2 15.17,81.38 v2(16.01,82.22)
GSEN2_INT1_R: length 2.6
  TOP w0.152: R505.1 22.25,70.98 21.5,71.72 v1(21.3,71.72) 21.15,71.72 20.89,71.99 U501.12
GSEN2_INT2: length 17.6
  TOP w0.152: R506.2 18.81,71.41 v2(18.56,71.66)
  L4 w0.152: v2(18.56,71.66) 17.42,72.8 16.32,72.8 15.44,73.68 15.44,74.65 14.75,75.34 14.75,79.16 v2(14.71,79.2)
  BOTTOM w0.152: IOBD2.28 12.9,80.7 13.57,80.03 13.99,80.03 14.71,79.32 v2(14.71,79.2) 14.71,79.18 14.62,79.09 14.62,78.76 v1(14.75,78.63) 15.34,78.63 16.23,77.74 RN602.4
GSEN2_INT2_C: length 19.6
  TOP w0.152: U601.38 6.55,85.44 v2(6.45,85.35)
  L3 w0.152: v2(6.45,85.35) 5.87,84.77 5.87,82.16 8.03,80 8.03,79.22 8.39,78.86 8.74,78.86 9.01,79.12 9.39,79.12 9.66,78.86 9.66,78.48 9.84,78.29 12.4,78.29 12.85,78.74 v2(12.89,78.74)
  BOTTOM w0.152: v2(12.89,78.74) 12.9,78.74 13.34,78.3 13.34,77.49 13.89,76.94 v1(14.44,76.94) 14.69,76.68 16.08,76.68 16.23,76.53 RN602.1
GSEN2_INT2_R: length 2.4
  TOP w0.152: R506.1 19.7,71.68 19.68,71.7 v1(19.68,71.77) 19.75,71.77 19.8,71.82 20.13,71.82 20.39,72.09 U501.11
GSEN_INT1_BD: length 18.2
  TOP w0.152: v2(19.61,83.04) 19.61,83.6 v1(19.59,83.63) 20.14,84.18 20.14,85.03 19.59,85.58 17.42,85.58 16.84,85 16.84,84.39 15.4,82.94 U601.18
  BOTTOM w0.152: SENSB1.6 25.79,86.25 24.94,85.4 21.97,85.4 v2(19.61,83.04)
GSEN_INT2_BD: length 17.5
  TOP w0.152: U601.19 15.34,83.44 16.54,84.64 16.54,85.09 17.31,85.86 19.7,85.86 20.58,84.98 v1(20.58,84.33) 20.58,83.2 v2(20.37,82.99)
  BOTTOM w0.152: v2(20.37,82.99) 22.45,85.07 25.22,85.07 25.9,85.75 SENSB1.5
GSEN_INT2_HUB_U: length 4
  TOP w0.152: U601.27 13.03,87.56 13.36,87.89 v1(14.3,87.89) 15.08,87.89 15.41,88.21 R626.1
GSENSOR_CS: length 2.4
  TOP w0.152: R504.2 22.85,72.31 v1(22.36,72.8) 21.94,73.22 U501.2
GSENSOR_SDO: length 3.4
  TOP w0.152: U501.3 22.11,73.72 v1(22.41,74.02) 22.41,73.94 23.2,73.15 R503.2 R502.2
GYRO_DRDY_BD: length 16.3
  TOP w0.152: R626.2 R627.2 16.75,88.32 16.96,88.12 17.78,88.12 18.93,86.98 19.71,86.98 21.94,84.74 v1(21.94,83.65) 21.94,83.22 v2(21.75,83.02)
  BOTTOM w0.152: v2(21.75,83.02) 23.48,84.75 SENSB1.3
GYRO_DRDY_BD_L: length 17.7
  TOP w0.152: R627.1 17.69,89.09 v1(18.6,88.18) 19.32,87.46 v2(19.38,87.46) ; v2(6.71,84.66) 7,84.94 U601.39
  L3 w0.152: v2(6.71,84.66) 9.84,87.78 19.06,87.78 v2(19.38,87.46)
GYRO_INT_BD: length 1.8
  TOP w0.152: TP606.1 20.6,85.55 19.67,86.48 R628.2
GYRO_INT_BD_L: length 4.9
  TOP w0.152: U601.20 15.28,83.94 16.18,84.84 16.18,85.3 17.11,86.23 v1(17.11,86.28) 17.12,86.28 17.3,86.46 R628.1
HALL_KB_DIS#: length 58.5
  TOP w0.102: v2(8.23,75.44) 8.73,74.93 8.73,74.88 10.93,72.69 10.93,71.84 10.11,71.02 v1(9.32,71.02) 9.26,71.08 C611.1 8.05,71.12 R620.1
  L4 w0.102: v2(8.23,75.44) 8.97,75.44 9.67,76.14 9.67,79.6 9.78,79.7 14.31,79.7 16.95,82.35 27.08,82.35 28.96,84.23 42.67,84.23 43.43,83.47 v2(45.56,83.47)
  BOTTOM w0.102: v2(45.56,83.47) 46.06,83.47 46.62,84.02 LIDSW2.3 ; IOBD2.24 10.8,78.7 8.38,76.28 8.38,75.59 v2(8.23,75.44)
HALL_KB_DIS#_C: length 1.6
  TOP w0.102: EC705.1 39.95,6.84 39.88,6.92 AFTP706.1
HUB_PA1: length 5.6
  TOP w0.152: U601.11 13.53,78.98 13.34,78.8 13.34,78.3 R606.1 12.85,76.91 v1(12.85,76.39) 12.41,76.39 11.56,75.54 R605.2
HUB_PA2: length 6
  TOP w0.152: U601.12 14.03,78.97 14.63,78.37 R604.1 14.94,78.59 15.44,78.59 15.92,78.11 15.92,76.75 v1(15.86,76.69) 15.69,76.53 R616.2
HUB_PA3: length 4.4
  TOP w0.152: U601.13 15.1,80.44 16.1,79.44 16.1,78.89 v1(16.08,78.87) 16.62,78.87 R614.1 16.4,78.04 R613.2
HUB_PA4: length 4
  TOP w0.152: U601.14 16.27,80.94 16.67,80.55 v1(16.67,80.44) 16.88,80.65 R612.1 R610.2
HUB_PA5: length 5.5
  TOP w0.152: 17.57,83.31 R608.2 ; 17.57,83.31 17.08,83.31 v1(16.68,82.91) 16.98,82.61 16.98,81.77 16.66,81.44 U601.15 ; 17.57,83.31 R611.1
HUB_PA6: length 6.8
  TOP w0.152: R607.2 17.53,85.1 v1(17.5,85.12) 17.5,84.27 R609.1 17.28,84.21 16.54,83.47 16.54,83.3 16.3,83.07 16.3,82.75 16.54,82.51 16.54,81.92 16.38,81.76 15.49,81.76 15.31,81.94 U601.16
HUB_USB20_CON_N7: length 30.9
  TOP w0.089: 21.64,81.22 15.14,74.71 15.14,73.67 15,73.54 14.15,73.54 14.02,73.66 v2(14.02,73.88) ; 21.64,81.22 22.6,82.18 22.6,85.12 16.59,91.13 14.47,91.13 14.37,91.04 14.37,90.72 14.3,90.65 13.78,90.65 R601.1 ; 21.64,81.22 v1(21.55,81.32)
  BOTTOM w0.089: v2(14.02,73.88) 14.02,73.71 13.88,73.57 12.78,73.57 12.65,73.7 IOBD2.14
HUB_USB20_CON_P7: length 31
  TOP w0.089: 22.84,84.33 22.84,85.22 16.69,91.37 R617.1 ; 22.84,84.33 22.84,82.08 15.38,74.61 15.38,73.57 15.1,73.29 14.23,73.29 v2(14.02,73.08) ; 22.84,84.33 v1(23,84.33)
  BOTTOM w0.089: v2(14.02,73.08) 13.76,73.33 12.78,73.33 12.65,73.2 IOBD2.13
JACK_PLUG: length 87.2
  L3 w0.254: v2(20.22,91.85) 20.32,91.85 20.34,91.87 23.11,91.87 23.54,91.44 26.54,91.44 26.97,91.01 30.58,91.01 34.8,86.79 34.8,38.41 35.05,38.15 v2(35.1,38.15)
  BOTTOM w0.254: v2(20.22,91.85) 16.52,91.85 13.9,89.23 12.82,89.23 12.29,88.7 12.29,88.45 12.04,88.2 IOBD2.43 ; v2(35.1,38.15) 35.41,38.15 35.46,38.1 37.93,38.1 38.88,37.16 ED302.1 41.79,37.16 v1(41.88,37.06) 42.69,37.06 43.75,36 HPMIC1.5
JACK_PLUG_DET: length 10.7
  BOTTOM w0.254: R307.1 33.09,31.98 R308.2 33.15,32.56 33.29,32.56 34.03,33.3 v1(34.03,33.38) 34.03,33.81 33.88,33.96 33.88,35.35 ; 33.88,35.35 34.69,34.55 36.52,34.55 37.19,35.21 37.85,35.21 38.1,34.96 HPMIC1.6 ; 33.88,35.35 ED303.2
KB_RESERVE: length 5.2
  TOP w0.102: v2(4.96,85.56) 4.4,86.12 TP601.1 ; v2(6.56,83.55) 6.95,83.94 U601.41
  L4 w0.102: v2(6.56,83.55) 6.2,83.55 4.96,84.79 v2(4.96,85.56)
KBC_PWRBTN#: length 103.8
  TOP w0.089: v2(8.81,75.92) 8.81,75.39 v1(10.51,73.69) 10.51,73.48 11.88,72.11 14.32,72.11 18.27,68.16 22.07,68.16 23.2,69.29 24.18,69.29 26.62,71.73 30.45,71.73 30.81,71.38 30.81,67.72 31.46,67.06 31.46,64.98 33.34,63.1 33.34,39.87 32.58,39.11 32.58,33.95 33.11,33.41 33.11,25.08 33.42,24.77 34.14,24.77 37.41,21.49 37.41,16.99 v1(39.95,14.45) 40.21,14.2 40.21,14.07 42.8,11.48 42.8,6.38 43.51,5.67 R701.1 C704.1
  BOTTOM w0.089: IOBD2.23 10.89,78.2 8.81,76.12 v2(8.81,75.92)
KBC_PWRBTN#_C: length 18.9
  TOP w0.089: R701.2 43.53,6.55 44.02,7.04 AFTP702.1 44.02,9.39 ED701.1 43.76,10 v2(43.33,10.42)
  BOTTOM w0.089: PWBD1.1 31.7,8 32.36,7.34 34.95,7.34 38.8,11.2 41.06,11.2 41.57,11.71 42.04,11.71 v2(43.33,10.42)
MCU_BOOT0: length 3
  TOP w0.152: R618.1 6.02,80.93 v1(6.45,81.37) 6.45,81.69 7.06,82.31 7.07,82.31 7.21,82.44 U601.44
MCU_OSCI: length 9.3
  TOP w0.089: X601.1 4.96,74.46 5.92,75.42 5.92,76.44 6.24,76.76 7.41,76.76 7.75,77.1 7.75,77.54 C603.1 8.46,77.56 R602.2 8.58,77.52 9.09,78.03 9.52,78.03 v1(9.96,78.47) 9.97,78.47 10.53,79.03 U601.5
MCU_OSCO: length 2.3
  TOP w0.089: R625.1 11.17,78.46 v1(11.18,78.47) 11.03,78.62 U601.6
MCU_OSCO_X601: length 4.8
  TOP w0.089: R625.2 R602.1 9.78,77.13 C601.1 9.54,76.49 v1(8.82,76.49) 8.67,76.49 8.16,75.97 X601.3
MCU_RST#: length 4.9
  TOP w0.089: C608.1 11.2,76.73 11.49,76.44 v1(11.51,76.44) 11.51,76.5 R615.1 11.64,77.74 11.64,78.67 11.53,78.78 U601.7
MODEL_ID: length 10.1
  BOTTOM w0.102: IOBD2.30 12.22,81.7 12.64,82.13 14.89,82.13 15.46,82.7 16.32,82.7 16.44,82.58 16.44,81.42 15.61,80.59 15.61,79.61 R802.1 15.64,79.26 16.22,78.67 v1(16.28,78.67)
RING2_HPMIC1: length 11
  L4 w1.016: 36.84,37.19 37.55,36.48 44.22,36.48 45.63,35.07 HPMIC1.2
  vias: v1(31.85,38.95) v3(34.34,37.17) v3(35.18,37.17)
RING2_R: length 56.5
  L3 w1.016: 32.59,43.05 32.59,46.09 32.19,46.49 32.19,85.62 29.8,88.01 21.44,88.01 20.03,89.42
  vias: v1(32.71,41.69) v2(31.81,42.25) v2(31.82,41.61) v3(18.98,90.91) v3(19.82,90.87)
SENSOR_I2C_SCL: length 37.8
  TOP w0.089: v1(8.7,78.38) v2(9.2,78.67) ; v2(18.87,70.11) 20.77,70.11 21.5,69.38 RN501.4 22.45,70.11 23.8,70.11 24.33,70.63 R507.1 ; v2(3.25,83.96) 3.76,83.45 R622.1
  L4 w0.14: v2(9.2,78.67) 9.15,78.61 9.15,78.45 7.66,76.97 7.66,74.81 9.68,72.79 10.65,72.79 11.43,72.01 11.43,71.88 12.46,70.86 17.79,70.86 18.54,70.11 v2(18.87,70.11)
  BOTTOM w0.089: v2(3.25,83.96) 5.48,81.73 5.48,79.19 6.86,77.82 8.21,77.82 9.06,78.67 v2(9.2,78.67)
SENSOR_I2C_SCL_2G: length 9.4
  TOP w0.089: RN601.4 4.93,88.67 5.59,88.01 v1(5.59,85.3) 5.59,84.38 R621.2 R622.2 5.98,83.12 6.82,83.12 7.14,83.44 U601.42
SENSOR_I2C_SCL_R: length 4
  TOP w0.089: R507.2 v1(23.44,70.56) 23.09,70.91 22.97,70.91 22.83,71.05 22.83,71.44 21.61,72.66 U501.1
SENSOR_I2C_SDA: length 41.8
  TOP w0.089: v2(18.84,69.42) 18.93,69.51 20.7,69.51 20.87,69.35 20.87,68.67 21.02,68.51 RN501.3 21.84,68.51 22.97,69.64 23.99,69.64 24.8,70.44 24.8,70.44 25.96,71.6 v1(25.96,72.07) 25.96,74.77 25.6,75.13 24.58,75.13 R508.1 ; R624.1 4.66,81.77 4.26,81.77 2.87,80.38 v2(2.87,80.29)
  L4 w0.14: v2(18.84,69.42) 18.49,69.42 17.57,70.33 6.68,70.33 5.97,71.05 5.97,72.95 4.92,73.99 4.92,79.8 4.43,80.29 4.06,80.29 4.06,80.29 v2(2.87,80.29)
SENSOR_I2C_SDA_2G: length 13.3
  TOP w0.089: v2(3.61,89.52) 3.61,89.95 v1(3.76,90.1) 4.47,90.81 RN601.3 ; R624.2 R623.2 6.15,82.61 6.2,82.56 v2(6.33,82.56) 6.96,82.56 7.35,82.94 U601.43
  BOTTOM w0.089: v2(6.33,82.56) 4.12,84.77 4.12,87.65 3.61,88.16 v2(3.61,89.52)
SENSOR_I2C_SDA_R: length 2.6
  TOP w0.089: R508.2 23.03,75.28 v1(22.55,75.28) 22.48,75.22 22.39,75.22 U501.4
SENSOR_KB_DIS: length 8.7
  TOP w0.102: U601.2 9.03,79.27 8.69,78.93 7.92,78.5 v1(7.48,78.5) 7.32,78.34 v2(6.94,78.34)
  BOTTOM w0.102: IOBD2.29 9.31,81.2 7.04,78.93 7.04,78.44 v2(6.94,78.34)
SLEEVE_HPMIC1: length 4.8
  TOP w1.016: HPMIC1.1 46.8,25.12 45.83,24.16 44.02,24.16 43.23,23.37
  vias: v1(42.42,22.6)
SLEEVE_R: length 80.7
  L3 w1.016: 33.64,36.3 33.3,36.64 33.3,39.89 33.86,40.46 33.86,85.75 29.79,89.82 23.54,89.82 23.29,90.06 ; 41.18,22.16 41.18,22.98 40.16,24.01 36.04,24.01 35,25.05 35,26.17 33.07,28.1 33.07,34.12 33.61,34.66
  vias: v1(36.29,37.15) v3(21,90.05) v3(21.84,90.08) v3(35.13,36.03) v3(35.11,35.19) v3(40.05,21.15) v3(40.92,21.16)
ST_SENSOR_I2C_SCL: length 39.7
  TOP w0.089: v1(23.62,85.66) v2(23.7,86.26) ; v2(3.33,85.84) 3.33,85.36 4.38,84.31 R621.1
  L3 w0.14: v2(23.7,86.26) 23.7,84.08 21.11,81.49 19.9,81.49 19.59,81.18 17.98,81.18 16.04,79.24 16.04,77.77 15.61,77.34 7.3,77.34 6.25,78.39 6.25,81.04 4.96,82.33 4.96,84.21 v2(3.33,85.84)
  BOTTOM w0.089: v2(23.7,86.26) 23.7,86.18 23.98,85.9 24.73,85.9 25.59,86.75 25.61,86.75 26.11,87.25 SENSB1.8
ST_SENSOR_I2C_SDA: length 37.5
  TOP w0.089: R623.1 3.61,82.61 v2(3.25,82.97) ; v1(24.81,85.9) v2(24.53,86.41)
  L3 w0.14: v2(24.53,86.41) 24.53,83.98 21.52,80.97 20.16,80.97 19.76,80.57 18.11,80.57 16.61,79.07 16.61,77.42 16.01,76.82 7.09,76.82 5.73,78.18 5.73,80.49 v2(3.25,82.97)
  BOTTOM w0.089: SENSB1.9 24.95,87.75 24.53,87.32 v2(24.53,86.41)
SWCLK: length 9
  TOP w0.152: v2(8.25,91.34) 8.35,91.25 9.76,91.25 TP604.1 ; U601.37 v2(6.75,85.94)
  L4 w0.152: v2(8.25,91.34) 8.28,91.32 8.28,87.47 v2(6.75,85.94)
SWDIO: length 7.4
  TOP w0.152: TP605.1 8.67,91.8 7.76,91.8 v2(7.59,91.63) ; v2(8.91,87.58) 8.92,87.58 9.2,87.58 9.53,87.26 U601.34
  L3 w0.152: v2(8.91,87.58) 8.61,87.58 7.95,88.24 7.95,90.78 7.59,91.14 v2(7.59,91.63)
USB2_USB20_CON_N3: length 25.4
  BOTTOM w0.089: 30.24,78.93 v1(30.24,78.76) ; 30.24,78.93 26.79,78.93 26.7,78.84 26.48,78.61 25.36,78.61 25.35,78.6 24.47,78.6 23.99,79.08 ED402.6 22.28,79.08 22.15,78.94 22.15,77.94 21.87,77.66 21.39,77.66 21.02,77.29 R407.2 ; 30.24,78.93 33.11,78.93 34.13,77.91 34.13,72.11 35.57,70.68 36.3,70.68 USB2.2
USB2_USB20_CON_P3: length 25.6
  BOTTOM w0.089: R408.2 21.02,78.17 21.29,77.9 21.77,77.9 21.9,78.04 21.9,79.04 22.4,79.54 23.87,79.54 24.54,78.87 25.04,78.87 25.25,79.08 ED402.1 25.72,79.03 26.5,79.03 26.64,79.17 28.19,79.17 ; 28.19,79.17 33.21,79.17 34.37,78.01 34.37,72.21 35.67,70.92 36.2,70.92 USB2.3 ; 28.19,79.17 v1(28.19,79.36)
USB2_USB20_N3: length 30.4
  BOTTOM w0.089: R407.1 19.59,77.29 19.31,77.57 18.39,77.57 18.08,77.27 18.08,70.74 ; 18.08,70.74 v1(18.26,70.74) ; 18.08,70.74 18.08,69.59 14.89,66.4 10.13,66.4 8.68,67.85 8.68,73.65 10.24,75.2 IOBD2.17
USB2_USB20_P3: length 29.7
  BOTTOM w0.089: 17.84,74.73 17.84,77.37 18.29,77.81 19.23,77.81 19.58,78.17 R408.1 ; 17.84,74.73 17.84,69.69 14.79,66.64 10.23,66.64 8.93,67.95 8.93,73.55 10.34,74.96 10.61,74.96 10.87,74.7 IOBD2.16 ; 17.84,74.73 v1(17.68,74.73)
USB3_USB20_CON_N4: length 25.2
  BOTTOM w0.089: 32.85,55.78 33.46,53.55 33.46,53.53 34.94,49.43 arc(35.11,49.16) 35.31,48.91 36.35,47.88 36.73,47.88 36.93,47.68 USB3.2 ; 32.85,55.78 32.61,56.69 arc(32.6,56.73) 32.6,56.77 32.6,56.77 32.6,57.43 32.38,57.65 ED403.6 32.38,59.67 31.89,60.16 31.89,61.3 32.01,61.43 32.01,63.05 31.98,63.23 31.41,64.46 28.8,67.07 28.8,67.71 28.38,68.13 27.72,68.13 R409.2 ; 32.85,55.78 v1(32.69,55.73)
USB3_USB20_CON_P4: length 25.5
  BOTTOM w0.089: 32.26,62.69 32.26,61.34 32.38,61.22 ED403.1 32.38,60.01 32.62,59.77 32.62,58.82 32.84,58.6 32.84,56.77 32.84,56.77 arc(32.84,56.76) 32.84,56.75 33.09,55.85 33.69,53.61 35.16,49.53 arc(35.31,49.29) 35.49,49.08 36.45,48.12 36.79,48.12 36.95,48.29 USB3.3 ; 32.26,62.69 32.26,63.08 32.21,63.31 31.61,64.6 29.04,67.17 29.04,67.81 28.39,68.46 28.39,68.69 28.23,68.86 R410.2 ; 32.26,62.69 v1(32.43,62.69)
USB3_USB20_N4: length 32.4
  BOTTOM w0.089: 22.6,68.34 25.81,68.34 26.1,68.05 R409.1 ; 22.6,68.34 19.97,68.34 19.78,68.15 17.82,68.15 15.24,65.56 9.77,65.56 7.85,67.48 7.85,74.2 10.35,76.7 IOBD2.20 ; 22.6,68.34 v1(22.6,68.19)
USB3_USB20_P4: length 31.7
  BOTTOM w0.089: 24.66,68.58 v1(24.66,68.73) ; 24.66,68.58 19.87,68.58 19.68,68.39 17.72,68.39 15.14,65.8 9.87,65.8 8.09,67.58 8.09,74.1 10.45,76.46 10.66,76.46 10.92,76.2 IOBD2.19 ; 24.66,68.58 25.81,68.58 26.09,68.86 R410.1
USB20_VCCA: length 17.6
  L4 w0.508: 36.94,67.35 USB2.1 36.3,68.18 ; 36.94,67.35 36.32,66.73 ; 36.94,67.35 35.93,67.35 ; 36.06,44.5 USB3.1 37.13,44.5 36.45,45.19
  BOTTOM w0.508: 36.9,44.5 36.32,43.92 ; 36.9,44.5 36.04,44.5 36.01,44.48 ; 36.9,44.5 36.93,44.5 ; v2(35.46,57.57) 35.03,57.13 33.62,57.13 33.33,57.43 ED403.5 ; 36.93,44.5 36.34,45.09 ; 36.93,44.5 USB3.1 ; v3(26.57,76.15) 25.3,76.15 24.34,77.11 24.34,77.56 23.78,78.12 ED402.5
  BOTTOM w1.016: USB2.1 35.46,67.97
  vias: v1(32.77,75.82) v1(32.79,73.64) v1(33.02,70.22) v3(28.78,75.57) v3(28.83,74.74) v3(29.75,75.65) v3(29.75,74.74) v3(31.6,45.68) v3(31.6,44.76) v3(31.6,43.9)
USB_2+: length 7.2
  TOP w0.089: 11.78,91.06 12.4,91.06 R617.2 ; 11.78,91.06 10.72,91.06 9.74,90.08 R603.1 9.74,88.78 10.14,88.37 10.14,87.37 10.03,87.25 U601.33 ; 11.78,91.06 v1(11.78,91.22)
USB_2-: length 6.9
  TOP w0.089: 10.21,90.22 10.82,90.82 12.38,90.82 R601.2 ; 10.21,90.22 v1(10.34,90.1) ; 10.21,90.22 9.98,89.98 9.98,89.49 10.18,89.28 10.18,88.67 10.39,88.47 10.39,87.4 10.53,87.26 U601.32
USB_OC#0: length 19.9
  L3 w0.14: v2(15.59,72.2) 16.7,71.08 19.62,71.08 20.16,70.54 25.29,70.54 27.17,72.42 v2(28.5,72.42)
  BOTTOM w0.089: U401.3 28.84,72.08 v2(28.5,72.42) ; v2(15.59,72.2) v1(14.12,72.2) IOBD2.11
USB_PWR_EN#: length 22.9
  L3 w0.14: v2(26.69,70.34) 25.73,70.34 25.66,70.27 19.9,70.27 19.35,70.82 16.07,70.82 15.15,71.74 15.15,71.99 15.14,72.01 15.14,72.39 15.15,72.41 15.15,74.89 v2(13.89,76.15)
  BOTTOM w0.089: IOBD2.22 12.75,77.7 13.79,76.66 13.79,76.24 13.88,76.15 v2(13.89,76.15) ; v2(26.69,70.34) v1(27.3,70.34) 27.36,70.39 U401.4
USBDISABLE: length 7.9
  TOP w0.152: v2(12.78,88.33) 12.37,87.92 v1(12.34,87.92) 11.18,87.92 11.03,87.77 11.03,87.49 11.03,87.48 U601.31 ; v2(8.88,88.22) 8.85,88.25 R603.2
  L3 w0.152: v2(12.78,88.33) 12.78,88.33 12.77,88.33 12.68,88.33 12.46,88.55 9.43,88.55 9.09,88.22 8.89,88.22 v2(8.88,88.22)
VOL_DOWN#: length 107.3
  TOP w0.102: v2(27.45,67.26) 27.81,66.91 28.9,66.91 32.89,62.91 32.89,40.06 32.13,39.3 32.13,39.11 32.13,38.92 32.13,33.76 32.66,33.23 32.66,24.89 33.29,24.26 34.01,24.26 36.95,21.31 36.95,8.91 37.34,8.52 39.08,8.52 R702.1 39.17,7.73 38.56,7.12 AFTP704.1 38.31,6.69 C702.2
  L3 w0.102: v2(27.45,67.26) 26.46,68.25 19.88,68.25 19.78,68.15 19.23,68.15 19.06,68.33 18.39,68.33 18.01,68.71 14.27,68.71 13.48,67.92 13.05,67.92 13.02,67.9 12.58,67.9 12.55,67.92 12.42,67.92 12.32,68.02 12.32,68.06 10.61,69.76 9.2,69.76 7.69,68.25 v2(7.03,68.25)
  BOTTOM w0.102: v2(7.03,68.25) 7.03,68.33 6.65,68.71 6.65,70.97 6.93,71.25 6.93,75.53 10.28,78.88 10.28,79.22 10.76,79.7 IOBD2.26
VOL_DOWN#_R: length 13.8
  TOP w0.102: v2(39.17,10.17) 39.27,10.27 39.27,10.9 v1(39.24,10.92) 38.88,10.92 38.78,10.82 38.78,10.47 38.05,9.74 ED703.1 39,9.33 R702.2
  BOTTOM w0.102: PWBD1.3 31.7,6 32.31,6.61 35.05,6.61 38.61,10.17 v2(39.17,10.17)
VOL_UP#: length 104.2
  TOP w0.102: C703.2 41.61,5.98 41.84,6.21 AFTP703.1 41.84,8.23 R703.1 41.61,8.47 42.18,9.04 42.18,11.55 37.18,16.55 37.18,21.4 34.07,24.51 33.36,24.51 32.89,24.99 32.89,33.32 32.36,33.85 32.36,39.02 32.36,39.02 32.36,39.2 33.12,39.96 33.12,63.01 28.92,67.21 28.24,67.21 28.14,67.31 v2(28.14,67.34)
  L3 w0.102: v2(28.14,67.34) 28.01,67.34 26.87,68.48 19.79,68.48 19.68,68.38 19.33,68.38 19.15,68.56 18.49,68.56 18.03,69.01 11.77,69.01 11.72,69.06 11.63,69.06 10.71,69.99 8.39,69.99 7.64,69.24 v2(7.08,69.24)
  BOTTOM w0.102: v2(7.08,69.24) 7.08,69.32 7.24,69.47 7.24,75.51 10.51,78.79 10.51,78.95 10.77,79.2 IOBD2.25
VOL_UP#_R: length 16.3
  TOP w0.102: R703.2 41.51,9.28 ED702.1 40.34,9.51 41.1,10.27 41.56,10.27 v1(41.81,10.52) 41.81,11.23 v2(41.75,11.29)
  BOTTOM w0.102: PWBD1.2 35.04,7 38.88,10.85 41.31,10.85 v2(41.75,11.29)

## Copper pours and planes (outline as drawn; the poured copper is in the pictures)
5V_S5 on BOTTOM: 10.46,67.08 9.47,68.07 9.47,70 9.75,70.28 10.39,70.28 10.77,69.9 12.13,69.9 12.39,70.16 12.93,70.16 14.05,69.02 14.05,67.24 13.89,67.08 ; 1 cut-out
5V_S5 on BOTTOM: 25.47,72.65 25.39,72.73 25.39,75.26 25.73,75.6 27.89,75.6 28.12,75.37 28.12,72.88 27.89,72.65 25.84,72.65 25.83,72.65 ; 1 cut-out
5V_S5 on L4: 8.89,66.81 9.32,66.38 25.66,66.38 28.39,69.12 28.39,74.32 27.45,75.26 26.01,75.26 25.63,74.88 25.63,71.91 24.15,70.44 9.73,70.44 8.89,69.6
GND on TOP: 11.86,72.44 10.94,73.36 10.94,73.83 9.38,75.39 9.38,75.88 9.49,76 10.82,76 10.89,75.93 10.89,75.41 11.33,74.98 11.88,74.98 13.13,76.23 14.6,76.23 14.93,75.9 14.93,75.16 14.27,74.5 13.69,74.5 13.48,74.3 13.48,72.9 13.03,72.44 ; 4 cut-outs
GND on TOP: outline of 176 points within 0.76,0.76 47.74,92.29 ; 17 cut-outs
GND on TOP: 6.61,87.84 6.15,88.3 6.15,89.21 6.28,89.34 7.42,89.34 7.5,89.26 7.5,87.97 7.37,87.84 ; 1 cut-out
GND on TOP: 36.62,25.17 35.89,25.91 35.89,39.6 35.43,40.06 35.43,42.09 35.84,42.5 35.84,47.63 35.53,47.93 35.53,88.32 31.82,92.03 31.82,92.25 31.86,92.29 39.99,92.29 40.87,91.93 41.23,91.05 41.23,87.56 41.74,86.31 42.99,85.8 47.5,85.8 47.67,85.73 47.74,85.56 47.74,80.86 46.03,80.86 45.14,80.49 44.77,79.6 44.77,78.36 39.39,78.36 37.98,78.8 37.12,77.6 37.12,64.1 37.98,62.9 39.39,63.34 44.77,63.34 44.77,55.51 39.39,55.51 37.98,55.95 37.12,54.75 37.12,41.25 37.98,40.05 39.39,40.49 44.77,40.49 44.77,37.46 45.14,36.56 46.03,36.2 47.5,36.2 47.67,36.13 47.74,35.96 47.74,34.31 37.9,34.31 37.01,33.94 36.64,33.05 36.64,26.95 36.72,26.5 36.95,26.11 36.95,25.17
GND on TOP: 10.77,88.52 10.67,88.62 10.67,89.87 10.84,90.05 11.88,90.05 11.99,89.94 11.99,89.41 11.55,88.98 11.55,88.57 11.5,88.52 ; 2 cut-outs
GND on TOP: 18.14,81.16 18.01,81.29 18.01,82.69 18.14,82.81 18.69,82.81 19.54,81.97 19.54,81.29 19.41,81.16 ; 1 cut-out
